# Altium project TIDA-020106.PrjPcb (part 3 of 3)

## Sheet ID1_LM74930.SchDoc: LM25143-Q1 Two Phases
size A4; Date: Not shown in title block; ApprovedBy: Not shown in title block; CheckedBy: Not shown in title block; Author: Not shown in title block; CompanyName: Not shown in title block; DrawnBy: Hely Zhang; Engineer: Not shown in title block; Organization: Not shown in title block; Address1: Not shown in title block; Address2: Not shown in title block; Address3: Not shown in title block; Address4: Not shown in title block; DocumentNumber: 1; Revision: Use project parameter SCH_Rev; SheetNumber: 3; SheetTotal: 15; PageSetup: Record=PageOptions¦CenterHorizontal=True¦CenterVertical=True¦PrintScale=0.96¦XCorrection=1.00¦YCorrection=1.00¦PrintKind=0¦BorderSize=5000000¦LeftOffset=0¦BottomOffset=0¦Orientation=2¦PaperLength=1000¦PaperWidth=1000¦Scale=100¦PaperSource=7¦PrintQuality=600¦MediaType=1¦DitherType=10¦PaperKind=11" x 17"¦PrintScaleMode=1
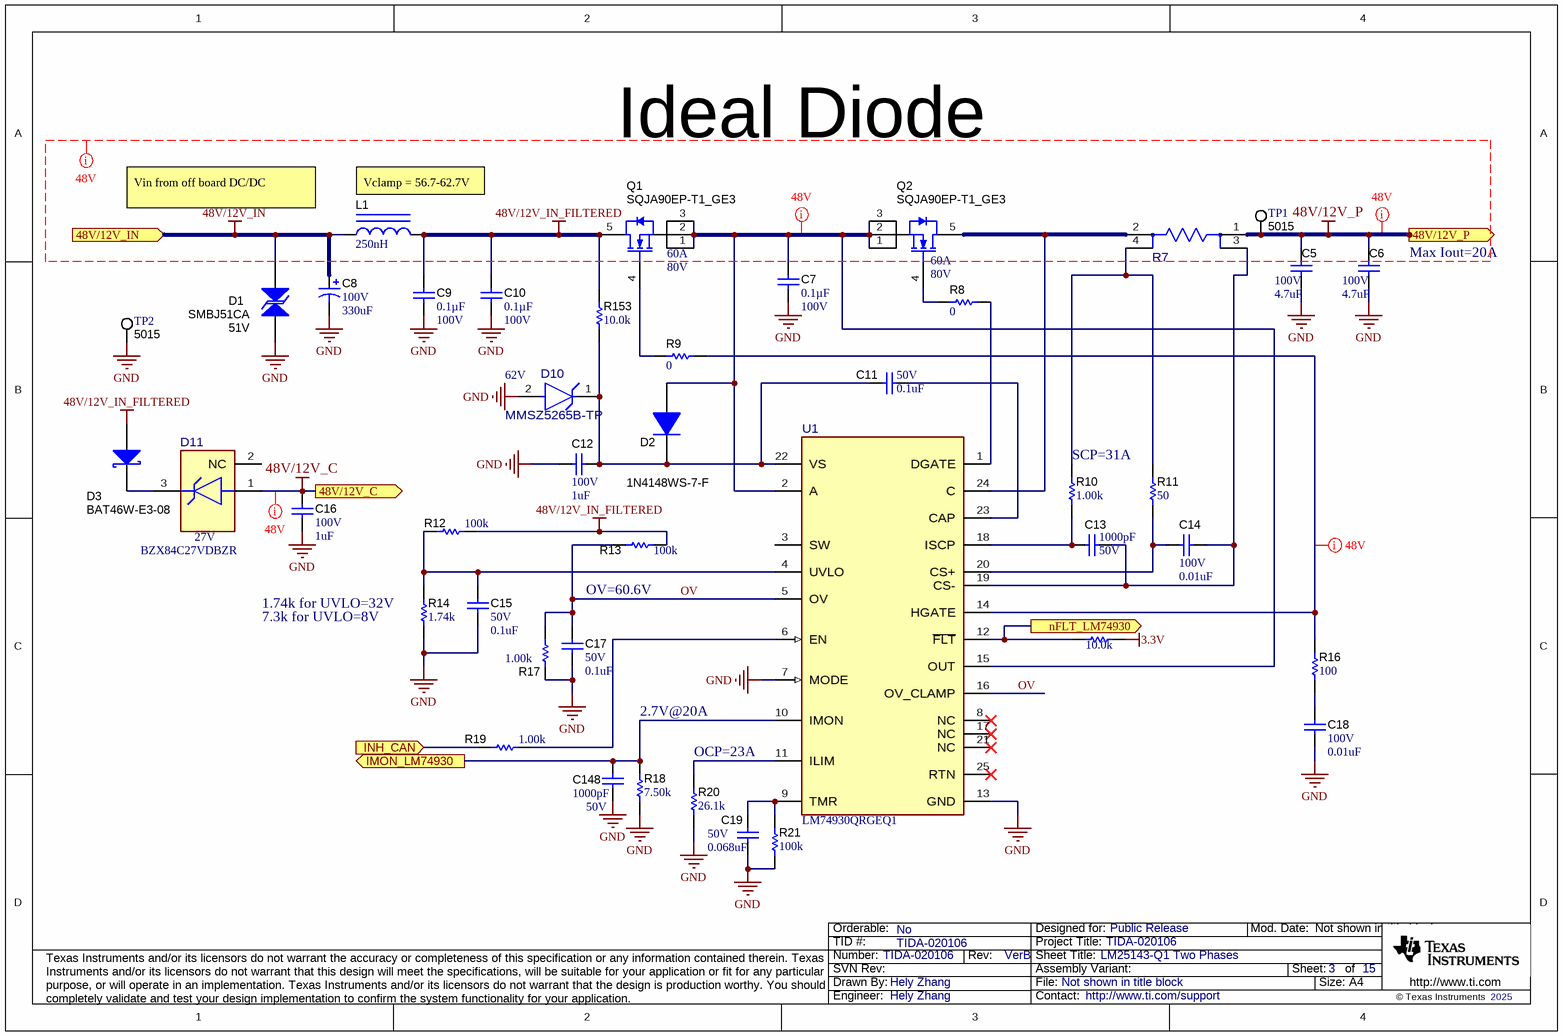
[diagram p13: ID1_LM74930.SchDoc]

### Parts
C5  VDC_V: 100V  ValueDisplayed: 4.7uF  [1210_220]  (hidden comment: GRM32DC72A475KE01L)
C6  VDC_V: 100V  ValueDisplayed: 4.7uF  [1210_220]  (hidden comment: GRM32DC72A475KE01L)
C7  ValueDisplayed: 0.1µF  VDC_V: 100V  [0603]  (hidden comment: GCJ188L8EL104KA07D)
C8  VDC_V: 100V  ValueDisplayed: 330uF  [CAPSMT_62_MN0]  (hidden comment: EMVE101GTR331MMN0S)
C9  ValueDisplayed: 0.1µF  VDC_V: 100V  [0603]  (hidden comment: GCJ188L8EL104KA07D)
C10  ValueDisplayed: 0.1µF  VDC_V: 100V  [0603]  (hidden comment: GCJ188L8EL104KA07D)
C11  VDC_V: 50V  ValueDisplayed: 0.1uF  [0402]  (hidden comment: GCM155R71H104KE02D)
C12  VDC_V: 100V  ValueDisplayed: 1uF  [1206_180]  (hidden comment: GCM31CR72A105KA03)
C13  ValueDisplayed: 1000pF  VDC_V: 50V  [0402]  (hidden comment: CGA2B2X8R1H102K050BA)
C14  VDC_V: 100V  ValueDisplayed: 0.01uF  [0402]  (hidden comment: CGA2B3X7S2A103K050BB)
C15  VDC_V: 50V  ValueDisplayed: 0.1uF  [0402]  (hidden comment: GCM155R71H104KE02D)
C16  VDC_V: 100V  ValueDisplayed: 1uF  [1206_180]  (hidden comment: GCM31CR72A105KA03)
C17  VDC_V: 50V  ValueDisplayed: 0.1uF  [0402]  (hidden comment: GCM155R71H104KE02D)
C18  VDC_V: 100V  ValueDisplayed: 0.01uF  [0402]  (hidden comment: CGA2B3X7S2A103K050BB)
C19  VDC_V: 50V  ValueDisplayed: 0.068uF  [0402]  (hidden comment: CGA2B3X7R1H683K050BB)
C148  ValueDisplayed: 1000pF  VDC_V: 50V  [0402]  (hidden comment: CGA2B2X8R1H102K050BA)
D1  SMBJ51CA  value 51V  [SMB-Bi]
D2  1N4148WS-7-F  [SOD-323]
D3  BAT46W-E3-08  [SOD-123]
D10  MMSZ5265B-TP  [FP-MMSZ5265B-TP_SOD123-MFG]
D11  Vz_V: 27V  [DBZ0003A-MFG]  (hidden comment: BZX84C27VDBZR)
L1  ValueDisplayed: 250nH  [WE-HCM_1390]  (hidden comment: 744309025)
Q1  SQJA90EP-T1_GE3  value 80V  IdsMax_A: 60A  [PowerPAK_SO-8L]
Q2  SQJA90EP-T1_GE3  value 80V  IdsMax_A: 60A  [PowerPAK_SO-8L]
R7  BVN-M-R001-1.0  [FP-BVN-M-R001-1.0_1612-MFG]  (value not drawn)
R8  ValueDisplayed: 0  [0402]  (hidden comment: CRCW04020000Z0ED)
R9  ValueDisplayed: 0  [0402]  (hidden comment: CRCW04020000Z0ED)
R10  ValueDisplayed: 1.00k  [0402]  (hidden comment: CRCW04021K00FKED)
R11  ValueDisplayed: 50  [0402]  (hidden comment: 504L50R0FTNCFT)
R12  ValueDisplayed: 100k  [0402]  (hidden comment: CRCW0402100KFKED)
R13  ValueDisplayed: 100k  [0402]  (hidden comment: CRCW0402100KFKED)
R14  ValueDisplayed: 1.74k  [0402]  (hidden comment: CRCW04021K74FKED)
R15  ValueDisplayed: 10.0k  [0402]  (hidden comment: CRCW040210K0FKED)
R16  ValueDisplayed: 100  [0402]  (hidden comment: CRCW0402100RFKED)
R17  ValueDisplayed: 1.00k  [0402]  (hidden comment: CRCW04021K00FKED)
R18  ValueDisplayed: 7.50k  [0402]  (hidden comment: CRCW04027K50FKED)
R19  ValueDisplayed: 1.00k  [0402]  (hidden comment: CRCW04021K00FKED)
R20  ValueDisplayed: 26.1k  [0402]  (hidden comment: CRCW040226K1FKED)
R21  ValueDisplayed: 100k  [0402]  (hidden comment: CRCW0402100KFKED)
R153  ValueDisplayed: 10.0k  [0402]  (hidden comment: CRCW040210K0FKED)
TP1  5015  [Testpoint_Keystone_Miniature]
TP2  5015  [Testpoint_Keystone_Miniature]
U1  LM74930QRGEQ1  [RGE0024T-MFG]

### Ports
48V/12V_C (out), 48V/12V_IN (in), 48V/12V_P (out), IMON_LM74930 (out), INH_CAN (in), nFLT_LM74930 (out)

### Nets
3.3V: R15.2
48V/12V_C: C16.1 D11.1(A) ; port 48V/12V_C
48V/12V_IN: C8.1(+) D1.2 L1.1 ; port 48V/12V_IN
48V/12V_IN_FILTERED: C9.2 C10.2 D3.2(A) L1.2 Q1.5(D) R12.2 R13.2 R153.1
48V/12V_P: C5.1 C6.1 R7.1 TP1.1 ; port 48V/12V_P
GND: C5.2 C6.2 C7.1 C8.2(-) C9.1 C10.1 C12.1 C15.2 C16.2 C17.2 C18.2 C19.2 C148.1 D1.1 D10.2(ANODE) R14.1 R17.1 R18.1 R20.1 R21.1 TP2.1 U1.7(MODE) U1.13(GND)
IMON_LM74930: C148.2 R18.2 U1.10(IMON) ; port IMON_LM74930
INH_CAN: R19.1 ; port INH_CAN
nFLT_LM74930: R15.1 U1.12(~{FLT}) ; port nFLT_LM74930
OV: C17.1 R13.1 R17.2 U1.5(OV) U1.16(OV_CLAMP)
NetC7_2: C7.2 D2.2(A) Q1.1(S) Q1.2(S) Q1.3(S) Q2.1(S) Q2.2(S) Q2.3(S) U1.2(A) U1.15(OUT)
NetC11_1: C11.1 U1.23(CAP)
NetC11_2: C11.2 C12.2 D2.1(K) D10.1(CATHODE) R153.2 U1.22(VS)
NetC13_1: C13.1 R10.1 U1.18(ISCP)
NetC13_2: C13.2 C14.2 R7.3 U1.19(CS-)
NetC14_1: C14.1 R11.1 U1.20(CS+)
NetC15_1: C15.1 R12.1 R14.2 U1.4(UVLO)
NetC18_1: C18.1 R16.1
NetC19_1: C19.1 R21.2 U1.9(TMR)
NetD3_1: D3.1(K) D11.3(K)
NetQ1_4: Q1.4(G) R9.2
NetQ2_4: Q2.4(G) R8.2
NetQ2_5: Q2.5(D) R7.2 U1.24(C)
NetR7_4: R7.4 R10.2 R11.2
NetR8_1: R8.1 U1.1(DGATE)
NetR9_1: R9.1 R16.2 U1.14(HGATE)
NetR19_2: R19.2 U1.6(EN)
NetR20_2: R20.2 U1.11(ILIM)

Not connected (* = marked no-connect by the designer): D11 2(NC); U1 3(SW) 8(NC)* 17(NC)* 21(NC)* 25(RTN)*

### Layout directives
net class 48V: 48V/12V_C, 48V/12V_IN, 48V/12V_IN_FILTERED, 48V/12V_P, NetC7_2, NetR9_1

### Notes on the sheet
- Ideal Diode
- (near L1) Vin from off board DC/DC
- (near L1) Vclamp = 56.7-62.7V
- (near C6) Max Iout=20A
- (near D10) 62V
- (near R10) SCP=31A
- (near R14) 1.74k for UVLO=32V
- (near R14) 7.3k for UVLO=8V
- OV=60.6V
- 2.7V@20A
- (near R20) OCP=23A

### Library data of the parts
C5 C6 = CMP-0009182-2: CAP, CERM, 4.7 uF, 100 V, +/- 10%, X7S, 1210; Manufacturer: MuRata; TaMin_C: -55°C; Polarized: N; SizeAreaWB_mm2: 14.7; Value1: Unknown; U/M: EA; Value: 4.7uF; TaMax_C: 125°C; SizeZ_mm: 2.2; SizeX_mm: 3.2; SizeY_mm: 2.5; Cap_Case: 1210; SizeArea_mm2: 8; Cap_F: 4.7µF; AEC Category: Q200
C7 C9 C10 = CMP-0860999-1: CAP, CERM, 0.1 µF, 100 V,+/- 10%, X8L, AEC-Q200 Grade 0, 0603; Manufacturer: MuRata; Cap_F: 100nF; TaMax_C: 150°C; SizeAreaWB_mm2: 4.68; SizeArea_mm2: 1.28; Value: 0.1uF; SizeZ_mm: 1; AEC Qualified: Y; SizeX_mm: 1.6; AEC Grade: 0; SizeY_mm: 0.8; U/M: EA; TaMin_C: -55°C; Polarized: N; AEC Category: Q200
C8 = CMP-0011277-1: CAP, AL, 330 uF, 100 V, +/- 20%, SMD; Manufacturer: Chemi-Con; TaMin_C: -40°C; Polarized: Y; SizeAreaWB_mm2: 441; Value1: Unknown; U/M: EA; Value: 330uF; TaMax_C: 105°C; SizeZ_mm: 21.5; SizeX_mm: 19; Cap_Case: MN0; SizeArea_mm2: 361; CompType: Capacitor; Cap_F: 330µF; IRMS_A: 980mA; AEC Category: Q200
C11 C15 C17 = CMP-0006356-2: CAP, CERM, 0.1 uF, 50 V, +/- 10%, X7R, AEC-Q200 Grade 1, 0402; Manufacturer: MuRata; TaMin_C: -55°C; Polarized: N; SizeAreaWB_mm2: 3; Value1: Unknown; U/M: EA; Value: 0.1uF; TaMax_C: 125°C; SizeZ_mm: 0.6; SizeX_mm: 1; SizeY_mm: 0.5; AEC Qualified: Y; Cap_F: 100nF; AEC Category: Q200
C12 C16 = CMP-0008815-2: CAP, CERM, 1 uF, 100 V, +/- 10%, X7R, AEC-Q200 Grade 1, 1206; Manufacturer: MuRata; TaMin_C: -55°C; Polarized: N; SizeAreaWB_mm2: 10.92; Value1: Unknown; U/M: EA; Value: 1uF; TaMax_C: 125°C; SizeZ_mm: 1.8; SizeX_mm: 3.2; SizeY_mm: 1.6; Cap_Case: 1206; SizeArea_mm2: 5.12; AEC Qualified: Y; Cap_F: 1µF; AEC Grade: 1; AEC Category: Q200
C13 C148 = CMP-0860997-1: CAP, CERM, 1000 pF, 50 V,+/- 10%, X8R, AEC-Q200 Grade 0, 0402; Manufacturer: TDK; SizeArea_mm2: 0.5; U/M: EA; SizeX_mm: 1; Polarized: N; AEC Grade: 0; AEC Qualified: Y; TaMin_C: -55°C; Value: 1000pF; TaMax_C: 150°C; SizeZ_mm: 0.6; Cap_F: 1nF; SizeAreaWB_mm2: 3; AEC Category: Q200
C14 C18 = CMP-0006333-1: CAP, CERM, 0.01 uF, 100 V, +/- 10%, X7S, AEC-Q200 Grade 1, 0402; Manufacturer: TDK; TaMin_C: -55°C; ESR_ohm: 0.4102; Polarized: N; SizeAreaWB_mm2: 3; Value1: 0.410191 ohm; U/M: EA; Value: 0.01uF; TaMax_C: 125°C; SizeZ_mm: 0.6; SizeX_mm: 1; SizeY_mm: 0.5; AEC Qualified: Y; Cap_F: 10nF; IRMS_A: 291.729mA; AEC Category: Q200
C19 = CMP-0006331-2: CAP, CERM, 0.068 uF, 50 V, +/- 10%, X7R, AEC-Q200 Grade 1, 0402; Manufacturer: TDK; TaMin_C: -55°C; ESR_ohm: 56.06m; Polarized: N; SizeAreaWB_mm2: 3; Value1: 0.05606 ohm; U/M: EA; TaMax_C: 125°C; SizeZ_mm: 0.6; SizeX_mm: 1; SizeY_mm: 0.5; AEC Qualified: Y; Cap_F: 68nF; IRMS_A: 684.724mA; AEC Category: Q200
D1 = CMP-0006055-3: Diode, TVS, Bi, 51 V, 82.4 Vc, SMB; Manufacturer: Bourns; AEC Category: Q101; AEC Qualified: N; Vbr_Max: 62.7V; Value1: 600W; Vbr_Min: 56.7V; Vc: 82.4V; Ipp: 7.3A
D2 = CMP-0079597-2: Diode, Switching, 75 V, 0.15 A, AEC-Q101, SOD-323; Manufacturer: Diodes Inc.; SizeX_mm: 2.7; Vf_V: 1.25V; AEC Qualified: Y; SizeArea_mm2: 3.645; AEC Category: Q101; SizeAreaWB_mm2: 8.695; Io_A: 150mA; SizeZ_mm: 1; Value1: 0.15A; SizeY_mm: 1.35; TJmax_C: 150°C; Vr_V: 75V; Value: 75V
D3 = CMP-0080760-2: Diode, Schottky, 100 V, 0.15 A, AEC-Q101, SOD-123; Manufacturer: Vishay-Semiconductor; SizeArea_mm2: 6.545; Io_A: 150mA; Vr_V: 100V; Value: 100V; SizeAreaWB_mm2: 13.095; AEC Qualified: Y; Vf_V: 1V; SizeZ_mm: 1.35; Value1: 0.15A; TJmax_C: 125°C; SizeY_mm: 1.7; SizeX_mm: 3.85; AEC Category: Q101
D10 = CMP-0128583-1: Zener Diode Single 62V 5% 185Ohm 500mW 2-Pin SOD-123 T/R; Manufacturer: MCC; AEC Qualified: No; SizeZ_mm: 1.35mm; TJmax_C: 150°C; Vf_V: 65.1V; Vr_V: 47V; Max Reverse Leakage Current: 0.1uA; Zener Impedance: 185Ω
D11 = CMP-0126395-1: Zener Diode 27 V 250 mW ±5% Surface Mount SOT-23-3; Manufacturer: Texas Instruments; AEC Qualified: No; SizeZ_mm: 1.12mm; TJmax_C: 150°C; Vf_V: 28.35V; Vr_V: 18.9V; Max Reverse Leakage Current: 0.03uA; Power_W: 250mW; Standoff Height: 0.01mm; TaMax_C: +150°C; TaMin_C: -55°C; Zener Impedance: 80Ω
L1 = CMP-0063911-1: Inductor, Shielded Drum Core, Ferrite, 250 nH, 50 A, 0.000165 ohm, SMD; Manufacturer: Wurth Elektronik; Isat: 81A @ 20% inductance drop; Irms: 50A @ 50C rise; Green_Lifecycle: Active; SizeAreaWB_mm2: 240; DCR_ohm: 165µ; Green_REACh: Passed; Value: 250nH; Imax_A: 50A; SizeZ_mm: 9.5; SizeX_mm: 14; SizeY_mm: 13; SizeArea_mm2: 182; AEC Category: Q200
Q1 Q2 = CMP-0086155-1: MOSFET, N-CH, 80 V, 60 A, AEC-Q101, PowerPAK_SO-8L; Alternate Manufacturer: None; Manufacturer: Vishay-Siliconix; SizeZ_mm: 1.14; SizeArea_mm2: 31.5495; ChMode: Enhancement; AEC Category: Q101; AEC Qualified: Y; Vgs_V: 20V; SizeAreaWB_mm2: 58.1095; Value2: 36 nC; Value1: ? ohm; QgTyp_nC: 36; SizeY_mm: 5.13; SizeX_mm: 6.15; ChType: N
R7 = CMP-0123675-1: 1 mOhms ±1% 7W Chip Resistor Wide 1612 (3831 Metric), 1216 Current Sense, Moisture Resistant; Manufacturer: Isabellenhuette; AEC Grade: Grade 0; AEC Qualified: Yes; Res_ohm: 1m; SizeZ_mm: 1.9mm; TempCo: 50ppm/°C; Value: 1m
R8 R9 = CMP-0026822-3: RES, 0, 5%, 0.063 W, AEC-Q200 Grade 0, 0402; Manufacturer: Vishay-Dale; Power_W: 63mW; TempCo: 200 ppm/C; Value_Code: 0000; Value: 0; EIA_Code: E24; SizeX_mm: 1; SizeY_mm: 0.5; SizeZ_mm: 0.6; Value2: 0.063W; AEC Qualified: Y; VDC_V: 50V; AEC Category: Q200
R10 R17 R19 = CMP-0026071-3: RES, 1.00 k, 1%, 0.063 W, AEC-Q200 Grade 0, 0402; Manufacturer: Vishay-Dale; Power_W: 63mW; TempCo: 100 ppm/C; Value_Code: 1k00; Value: 1.00k; EIA_Code: E96; Res_ohm: 1k; SizeX_mm: 1; SizeY_mm: 0.5; SizeZ_mm: 0.6; Value2: 0.063W; AEC Qualified: Y; VDC_V: 50V; AEC Category: Q200; AEC Grade: 0
R11 = CMP-0025948-2: RES, 50, 1%, 0.125 W, AEC-Q200 Grade 1, 0402; Manufacturer: AT Ceramics; Power_W: 125mW; TempCo: 150 ppm/C; Value_Code: 50R0; U/M: EA; Value: 50; SizeX_mm: 1; SizeY_mm: 0.5; SizeZ_mm: 0.6; Value2: 0.125W; AEC Qualified: Y; AEC Category: Q200
R12 R13 R21 = CMP-0025950-3: RES, 100 k, 1%, 0.063 W, AEC-Q200 Grade 0, 0402; Manufacturer: Vishay-Dale; Power_W: 63mW; TempCo: 100 ppm/C; Value: 100k; EIA_Code: E96; SizeX_mm: 1; SizeY_mm: 0.5; SizeZ_mm: 0.6; Value2: 0.063W; AEC Qualified: Y; VDC_V: 50V; AEC Category: Q200; AEC Grade: 0
R14 = CMP-0026094-3: RES, 1.74 k, 1%, 0.063 W, AEC-Q200 Grade 0, 0402; Manufacturer: Vishay-Dale; Power_W: 63mW; TempCo: 100 ppm/C; Value_Code: 1k74; Value: 1.74k; EIA_Code: E96; SizeX_mm: 1; SizeY_mm: 0.5; SizeZ_mm: 0.6; Value2: 0.063W; AEC Qualified: Y; VDC_V: 50V; AEC Category: Q200; AEC Grade: 0
R15 R153 = CMP-0025958-3: RES, 10.0 k, 1%, 0.063 W, AEC-Q200 Grade 0, 0402; Manufacturer: Vishay-Dale; Power_W: 63mW; TempCo: 100 ppm/C; Value_Code: 10k0; Value: 10.0k; EIA_Code: E96; Res_ohm: 10k; SizeX_mm: 1; SizeY_mm: 0.5; SizeZ_mm: 0.6; Value2: 0.063W; AEC Qualified: Y; VDC_V: 50V; AEC Category: Q200; AEC Grade: 0
R16 = CMP-0025951-3: RES, 100, 1%, 0.063 W, AEC-Q200 Grade 0, 0402; Manufacturer: Vishay-Dale; Power_W: 63mW; TempCo: 100 ppm/C; Value_Code: 100R; Value: 100; EIA_Code: E96; SizeX_mm: 1; SizeY_mm: 0.5; SizeZ_mm: 0.6; Value2: 0.063W; AEC Qualified: Y; VDC_V: 50V; AEC Category: Q200; AEC Grade: 0
R18 = CMP-0026555-2: RES, 7.50 k, 1%, 0.063 W, AEC-Q200 Grade 0, 0402; Manufacturer: Vishay-Dale; Power_W: 63mW; TempCo: 100 ppm/C; Value_Code: 7k50; Value: 7.50k; EIA_Code: E96; Res_ohm: 7.5k; SizeX_mm: 1; SizeY_mm: 0.5; SizeZ_mm: 0.6; Value2: 0.063W; AEC Qualified: Y; VDC_V: 50V; AEC Category: Q200; AEC Grade: 0
R20 = CMP-0026207-2: RES, 26.1 k, 1%, 0.063 W, AEC-Q200 Grade 0, 0402; Manufacturer: Vishay-Dale; Power_W: 63mW; TempCo: 100 ppm/C; Value_Code: 26k1; Value: 26.1k; EIA_Code: E96; SizeX_mm: 1; SizeY_mm: 0.5; SizeZ_mm: 0.6; Value2: 0.063W; AEC Qualified: Y; VDC_V: 50V; AEC Category: Q200; AEC Grade: 0
TP1 TP2 = CMP-0055152-1: Test Point, Miniature, SMT; Manufacturer: Keystone; CNHeader: FALSE; Green_Lifecycle: Active; Green_REACh: Passed; CT: TRUE
U1 = CMP-0021701-1: Ideal Diode Surge Stopper with Circuit breaker, overvoltage protection and fault output; Manufacturer: Texas Instruments; SizeZ_mm: 1mm; AEC Qualified: Yes; AEC Grade: Grade 1; Max Supply Voltage: 65V; Min Supply Voltage: 3V; Nominal Supply Current: 650-700uA; Number Of Outputs: 1; Standoff Height: 0mm; TaMax_C: +125°C; TaMin_C: -40°C; TJmax_C: +150°C

## Sheet Cover - VerB.SchDoc: Cover
size 431 x 279 mm; Date: Not shown in title block; ApprovedBy: Not shown in title block; CheckedBy: Not shown in title block; Author: Not shown in title block; CompanyName: Not shown in title block; Engineer: Not shown in title block; Organization: Not shown in title block; Address1: Not shown in title block; Address2: Not shown in title block; Address3: Not shown in title block; Address4: Not shown in title block; DocumentNumber: 1; Revision: Use project parameter SCH_Rev; SheetNumber: 15; SheetTotal: 15; PageSetup: Record=PageOptions¦CenterHorizontal=True¦CenterVertical=True¦PrintScale=1.00¦XCorrection=1.00¦YCorrection=1.00¦PrintKind=0¦BorderSize=5000000¦LeftOffset=0¦BottomOffset=0¦Orientation=2¦PaperLength=1000¦PaperWidth=1000¦Scale=100¦PaperSource=15¦PrintQuality=600¦MediaType=1¦DitherType=10¦PaperKind=Letter¦PrintScaleMode=1
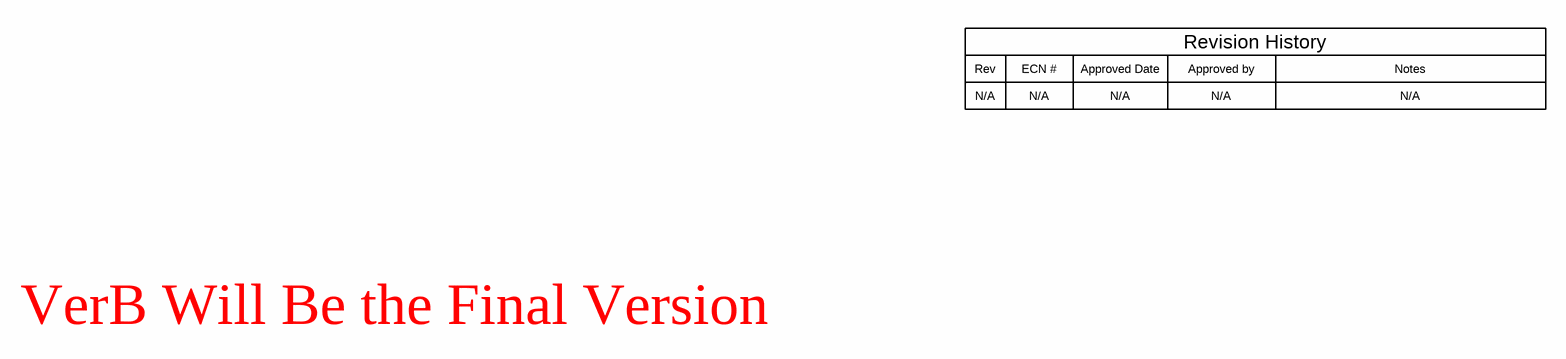
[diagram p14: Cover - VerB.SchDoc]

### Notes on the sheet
- Rev
- N/A
- ECN #
- Approved Date
- Approved by
- Revision History
- Notes
- VerB Will Be the Final Version

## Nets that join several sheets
1.25V: GPIO_Power (18 pins), PMIC (6 pins)
3.3V: Main (J10.1), DC_DC (R31.1), Clock_Reset (C121.1 C122.1 J23.1 Y1.4), GPIO_Power (24 pins), CAN (C103.1 C107.1 U8.5 U10.5), Sensor (10 pins), PMIC (6 pins), EPB (7 pins), BLDC (R54.1 R62.2), ID1_LM74930 (R15.2)
3.3Vref: ADC (L7.1 L8.1), GPIO_Power (C134.1 L10.2), PMIC (C44.2 C49.1 R39.1 TP7.1), BLDC (C83.1 U5.23)
5V: CAN (C101.1 C105.1 U8.3 U10.3), PMIC (C46.2 C51.1 R38.1 TP6.1), EPB (C92.2 U6.5)
5Vp1: Main (C4.1 J15.1 R6.2), PMIC (C47.2 C52.1 R41.1 TP9.1)
5Vp2: Main (C3.2 J11.1 R5.1), PMIC (C45.2 C50.1 R40.1 TP8.1)
12V: DC_DC (5 pins), ADC (R130.1), CAN (R97.2), PMIC (9 pins), EPB (C89.2 U6.1), BLDC (R51.2)
48V/12V_C: CAN (R99.2), ID1_LM74930 (C16.1 D11.1)
48V/12V_IN: Main (J3.1), ID1_LM74930 (C8.1 D1.2 L1.1)
48V/12V_P: DC_DC (9 pins), EPB (Q11.5), BLDC (13 pins), ID1_LM74930 (C5.1 C6.1 R7.1 TP1.1)
GND: Main (10 pins), DC_DC (19 pins), Clock_Reset (6 pins), ADC (6 pins), GPIO_Power (32 pins), CAN (17 pins), Sensor (10 pins), PMIC (40 pins), EPB (18 pins), BLDC (26 pins), ID1_LM74930 (23 pins)
BOOT1: Main (J10.3), GPIO_Power (R147.2 R149.2 U14.80)
CAN1H: Main (J17.1), CAN (L5.2 R98.1 R100.2 U9.2)
CAN1L: Main (J18.1), CAN (L5.1 R103.1 R105.1 U9.1)
CAN2H: Main (J19.1), CAN (L6.2 R109.1 R110.2 U11.1)
CAN2L: Main (J20.1), CAN (L6.1 R113.1 R115.1 U11.2)
CLK_DRV3263: GPIO_Power (R143.1), BLDC (U5.19)
CLK_PMIC: GPIO_Power (R142.2), PMIC (U3.33)
CLKEPB: Clock_Reset (R135.1), EPB (U6.11 U7.13)
CUTOFF_ASCIN: GPIO_Power (U14.84), BLDC (Q6.2 R53.1)
Cutoff_EPB: EPB (R85.1), BLDC (Q6.3 R57.1)
DRVOFF_DRV3263: GPIO_Power (U14.87), BLDC (U5.9)
DRVOFF_EPB: GPIO_Power (U14.2), EPB (R90.1)
EN_CAN1: ADC (U14.13), CAN (R107.1)
EN_CAN2: ADC (U14.41), CAN (R117.1)
FORCE_SENSOR_SENT: Main (C1.2 R1.1 R3.2), ADC (R128.2), GPIO_Power (R145.2)
IMON_LM74930: ADC (U14.35), ID1_LM74930 (C148.2 R18.2 U1.10)
IN1_EPB: GPIO_Power (U14.98), EPB (R94.1)
IN2_EPB: ADC (U14.11), EPB (R93.1)
INH_CAN: DC_DC (R26.1), CAN (D6.1 D7.1 R156.1 TP19.1), PMIC (R36.1), ID1_LM74930 (R19.1)
Isense_EPB: ADC (U14.10), EPB (C100.2 D12.2 R95.2 U7.2)
MCU_ERRORSTS: Clock_Reset (R134.1 R136.1), PMIC (U3.18)
MOS_LM68645: DC_DC (R154.2), GPIO_Power (U14.64)
nCS_DRV3263: GPIO_Power (U14.99), BLDC (U5.20)
nFAULT_CAN1: ADC (U14.29), CAN (U8.8)
nFAULT_CAN2: ADC (U14.28), CAN (U10.8)
nFAULT_EPB: GPIO_Power (U14.94), EPB (C99.2 R92.2 U7.1)
nFLT_DRV3263: GPIO_Power (U14.85), BLDC (R62.1 U5.22)
nFLT_LM74930: Clock_Reset (U14.68), ID1_LM74930 (R15.1 U1.12)
nSCS_EPB: GPIO_Power (U14.4), EPB (U7.12)
nSCS_PMIC: GPIO_Power (U14.57), PMIC (U3.36)
nSCS_WSS: ADC (U14.38), EPB (U6.12)
nSLEEP_DRV3263: GPIO_Power (U14.86), BLDC (U5.21)
nSTB_CAN: ADC (U14.40), CAN (R106.1 R116.1)
nXRS_DSP: Clock_Reset (C120.1 U14.71), PMIC (U3.13)
OUTA_EPB: Main (J5.1), EPB (U7.7)
OUTB_EPB: Main (J6.1), EPB (U7.5)
PEDAL_SENSOR_SENT: Main (C2.1 R2.2 R4.2), ADC (R129.2), GPIO_Power (R144.2)
PG_LM68645: DC_DC (R31.2 U2.2), GPIO_Power (U14.62)
PMIC_DIAG_OUT: GPIO_Power (U14.50), PMIC (C55.1 R43.2)
PWMAH: GPIO_Power (U14.92), BLDC (U5.11)
PWMAL: GPIO_Power (U14.93), BLDC (U5.12)
PWMBH: GPIO_Power (U14.90), BLDC (U5.13)
PWMBL: GPIO_Power (U14.91), BLDC (U5.14)
PWMCH: GPIO_Power (U14.88), BLDC (U5.15)
PWMCL: GPIO_Power (U14.89), BLDC (U5.16)
RX_CAN1: GPIO_Power (U14.58), CAN (R108.1 TP22.1)
RX_CAN2: GPIO_Power (U14.61), CAN (R118.1 TP23.1)
SDI_DRV3263: GPIO_Power (R141.1), BLDC (U5.18)
SDI_PMIC: GPIO_Power (R140.2), PMIC (U3.35)
SDIEPB: Clock_Reset (R133.1), EPB (U6.10 U7.14)
SDO_DRV3263: GPIO_Power (U14.97), BLDC (R59.1)
SDO_PMIC: GPIO_Power (U14.54), PMIC (R42.1)
SDOEPB: ADC (U14.39), EPB (R89.1 R96.1)
SHA: Main (J7.1), BLDC (7 pins)
SHB: Main (J8.1), BLDC (7 pins)
SHC: Main (J9.1), BLDC (7 pins)
SOA_DRV3263: ADC (U14.17), BLDC (C78.1 R71.1)
SOB_DRV3263: ADC (U14.23), BLDC (C79.1 R76.1)
SOC_DRV3263: ADC (U14.22), BLDC (C80.1 R77.1)
TMAG_COSP1: ADC (U14.20), Sensor (C111.1 R121.2)
TMAG_COSP2: ADC (U14.16), Sensor (C114.1 R125.2)
TMAG_Q01: GPIO_Power (U14.76), Sensor (R120.2 U12.4)
TMAG_Q02: GPIO_Power (U14.82), Sensor (R124.2 U13.4)
TMAG_Q11: GPIO_Power (U14.77), Sensor (R122.2 U12.5)
TMAG_Q12: GPIO_Power (U14.83), Sensor (R126.2 U13.5)
TMAG_SINP1: ADC (U14.21), Sensor (C110.1 R119.2)
TMAG_SINP2: ADC (U14.24), Sensor (C113.1 R123.2)
TX_CAN1: GPIO_Power (U14.59), CAN (R101.1 TP17.1)
TX_CAN2: GPIO_Power (U14.60), CAN (R111.1 TP18.1)
UART_RX: Main (J10.2), GPIO_Power (U14.75)
WSN: Main (J2.1), EPB (C94.2 D5.1 R88.2)
WSP: Main (J1.1), EPB (C90.2 D5.2 R86.2)
WSSO: ADC (U14.31), EPB (C88.2 R84.2)

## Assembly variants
12V: not fitted C25 C26 C29 C30 C70 C71 C84 C85 C86 C87 D13 FID1 FID2 FID3 L2 Q3 Q12 R23 R25 R26 R27 R28 R29 R30 R31 R32 R33 R34 R35 R51 R97 R98 R105 R109 R115 R128 R129 R146 R149 R150 R154 R155 U2; alternate parts U11 -> CMP-0125988-1, U5 -> CMP-0128057-1, U9 -> CMP-0125988-1, U8 -> CMP-0013356-2, U10 -> CMP-0013356-2
48V: not fitted C63 C70 C71 C84 C85 C86 C87 Q6 R22 R53 R58 R97 R98 R105 R109 R115 R128 R129 R146 R149 R150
